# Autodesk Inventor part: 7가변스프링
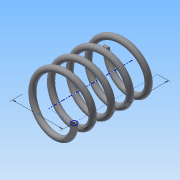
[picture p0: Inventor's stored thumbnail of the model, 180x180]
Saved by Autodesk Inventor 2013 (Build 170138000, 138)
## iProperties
Created: 2015-03
Part Number: 7가변스프링
Material: 강철, 탄소
Document SubType Name: Modeling
Designer: Administrator
Density: 1 g/cm^3
Author: Administrator
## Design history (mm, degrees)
sketch "스케치1"
  geometry: L1 (0, 0)-(17.5, 0); L2 (17.5, 0)-(17.5, 43.5); L3 (17.5, 43.5)-(0, 43.5); L4 (0, 43.5)-(0, 0); C1 r 2 at (17.5, 0)
  constraints: 8 end point, 2 parallel, 1 centre point, 1 coincident, 1 horizontal, 1 perpendicular
  dimensions: "d0" = 43.5 distance of L1.end L2.end (derived); "d2" = 35 diameter of L2 L4; "d3" = 4 diameter of C1
feature "코일1" sketch "스케치1" pitch "d4" = 10; turns "d6" = 4.5; dims "d5" = 43.5 (= d0), "d7" = 0, angle "d8" = 90 deg, angle "d9" = 90 deg, "d10" = 0, "d11" = 0
sketch "스케치2"
  geometry: L1 (-19.5, 0)-(-15.5, 0) reference; 1 further point
  constraints: 1 horizontal alignment
extrude "돌출1" cut sketch "스케치2" stored distance "d12" = 10; taper "d13" = 0 deg
node "작업 평면1"
sketch "스케치3"
  geometry: L1 (-19.5, 0)-(-15.5, 0) reference; 1 further point
  constraints: 1 horizontal alignment
extrude "돌출2" cut sketch "스케치3" stored distance "d15" = 10; taper "d16" = 0 deg
node "솔리드1"
node "절단 모서리 투영1"
node "절단 모서리 투영2"
other parameters: "d14" = -43.5 (= -d0)
